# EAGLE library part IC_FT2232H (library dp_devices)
DUAL HIGH SPEED USB TO MULTIPURPOSE UART/FIFO IC
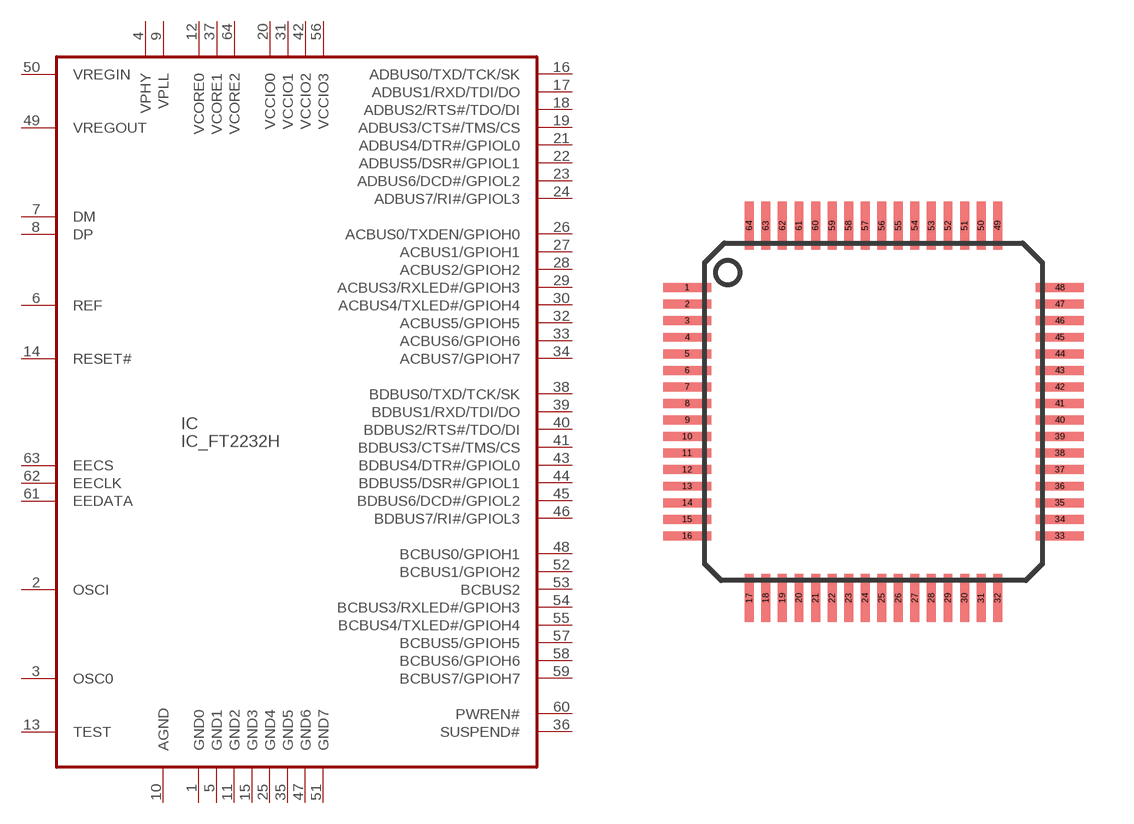
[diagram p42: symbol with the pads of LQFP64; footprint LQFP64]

Designator prefix IC

## IC_FT2232H  [LQFP64]
1  GND0
2  OSCI
3  OSC0
4  VPHY
5  GND1
6  REF
7  DM
8  DP
9  VPLL
10  AGND
11  GND2
12  VCORE0
13  TEST
14  RESET#
15  GND3
16  ADBUS0/TXD/TCK/SK
17  ADBUS1/RXD/TDI/DO
18  ADBUS2/RTS#/TDO/DI
19  ADBUS3/CTS#/TMS/CS
20  VCCIO0
21  ADBUS4/DTR#/GPIOL0
22  ADBUS5/DSR#/GPIOL1
23  ADBUS6/DCD#/GPIOL2
24  ADBUS7/RI#/GPIOL3
25  GND4
26  ACBUS0/TXDEN/GPIOH0
27  ACBUS1/GPIOH1
28  ACBUS2/GPIOH2
29  ACBUS3/RXLED#/GPIOH3
30  ACBUS4/TXLED#/GPIOH4
31  VCCIO1
32  ACBUS5/GPIOH5
33  ACBUS6/GPIOH6
34  ACBUS7/GPIOH7
35  GND5
36  SUSPEND#
37  VCORE1
38  BDBUS0/TXD/TCK/SK
39  BDBUS1/RXD/TDI/DO
40  BDBUS2/RTS#/TDO/DI
41  BDBUS3/CTS#/TMS/CS
42  VCCIO2
43  BDBUS4/DTR#/GPIOL0
44  BDBUS5/DSR#/GPIOL1
45  BDBUS6/DCD#/GPIOL2
46  BDBUS7/RI#/GPIOL3
47  GND6
48  BCBUS0/GPIOH1
49  VREGOUT
50  VREGIN
51  GND7
52  BCBUS1/GPIOH2
53  BCBUS2
54  BCBUS3/RXLED#/GPIOH3
55  BCBUS4/TXLED#/GPIOH4
56  VCCIO3
57  BCBUS5/GPIOH5
58  BCBUS6/GPIOH6
59  BCBUS7/GPIOH7
60  PWREN#
61  EEDATA
62  EECLK
63  EECS
64  VCORE2

## Footprint LQFP64 (pad centres in mm)
LQFP64 Richard Myrick T. Arellaga March2010
smd 1.45 x 0.27: 1 -5.625,3.75; 2 -5.625,3.25; 3 -5.625,2.75; 4 -5.625,2.25; 5 -5.625,1.75; 6 -5.625,1.25; 7 -5.625,0.75; 8 -5.625,0.25; 9 -5.625,-0.25; 10 -5.625,-0.75; 11 -5.625,-1.25; 12 -5.625,-1.75; 13 -5.625,-2.25; 14 -5.625,-2.75; 15 -5.625,-3.25; 16 -5.625,-3.75; 33 5.625,-3.75; 34 5.625,-3.25; 35 5.625,-2.75; 36 5.625,-2.25; 37 5.625,-1.75; 38 5.625,-1.25; 39 5.625,-0.75; 40 5.625,-0.25; 41 5.625,0.25; 42 5.625,0.75; 43 5.625,1.25; 44 5.625,1.75; 45 5.625,2.25; 46 5.625,2.75; 47 5.625,3.25; 48 5.625,3.75
smd 0.27 x 1.45: 17 -3.75,-5.625; 18 -3.25,-5.625; 19 -2.75,-5.625; 20 -2.25,-5.625; 21 -1.75,-5.625; 22 -1.25,-5.625; 23 -0.75,-5.625; 24 -0.25,-5.625; 25 0.25,-5.625; 26 0.75,-5.625; 27 1.25,-5.625; 28 1.75,-5.625; 29 2.25,-5.625; 30 2.75,-5.625; 31 3.25,-5.625; 32 3.75,-5.625; 49 3.75,5.625; 50 3.25,5.625; 51 2.75,5.625; 52 2.25,5.625; 53 1.75,5.625; 54 1.25,5.625; 55 0.75,5.625; 56 0.25,5.625; 57 -0.25,5.625; 58 -0.75,5.625; 59 -1.25,5.625; 60 -1.75,5.625; 61 -2.25,5.625; 62 -2.75,5.625; 63 -3.25,5.625; 64 -3.75,5.625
